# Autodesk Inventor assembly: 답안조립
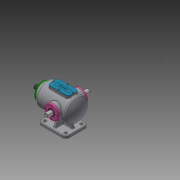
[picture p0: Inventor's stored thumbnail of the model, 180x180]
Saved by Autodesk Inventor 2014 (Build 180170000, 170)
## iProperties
Created: 2021-11
Part Number: 답안조립
Document SubType Name: Assembly
Designer: kb542-02
Author: kb542-02
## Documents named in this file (15)
- C:\Users\kb542-02\Desktop\711106V1007\답안조립.iam
- C:\Users\kb542-02\Desktop\711106V1007\본체.ipt
- C:\Users\kb542-02\Desktop\711106V1007\베어링 6205.ipt
- 베어링 6205.ipt
- C:\Users\kb542-02\Desktop\711106V1007\볼트 M4x0.7.ipt
- C:\Users\kb542-02\Desktop\711106V1007\부시.ipt
- C:\Users\kb542-02\Desktop\711106V1007\상부커버.ipt
- C:\Users\kb542-02\Desktop\711106V1007\슬라이드 커버.ipt
- C:\Users\kb542-02\Desktop\711106V1007\슬라이드.ipt
- C:\Users\kb542-02\Desktop\711106V1007\오일실.ipt
- 오일실.ipt
- C:\Users\kb542-02\Desktop\711106V1007\육각머리볼트 M4.ipt
- C:\Users\kb542-02\Desktop\711106V1007\축 커버.ipt
- C:\Users\kb542-02\Desktop\711106V1007\편심축.ipt
- C:\Users\kb542-02\Desktop\711106V1007\축 커버_MIR.ipt
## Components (16 placed, 1 different names)
1. M4x0.7:2
2. M4x0.7:8
3. M4x0.7:9
4. M4x0.7:10
5. M4x0.7:1
6. M4x0.7:5
7. M4x0.7:6
8. M4x0.7:7
9. M4x0.7:3
10. M4x0.7:11
11. M4x0.7:12
12. M4x0.7:13
13. M4x0.7:4
14. M4x0.7:14
15. M4x0.7:15
16. M4x0.7:16
